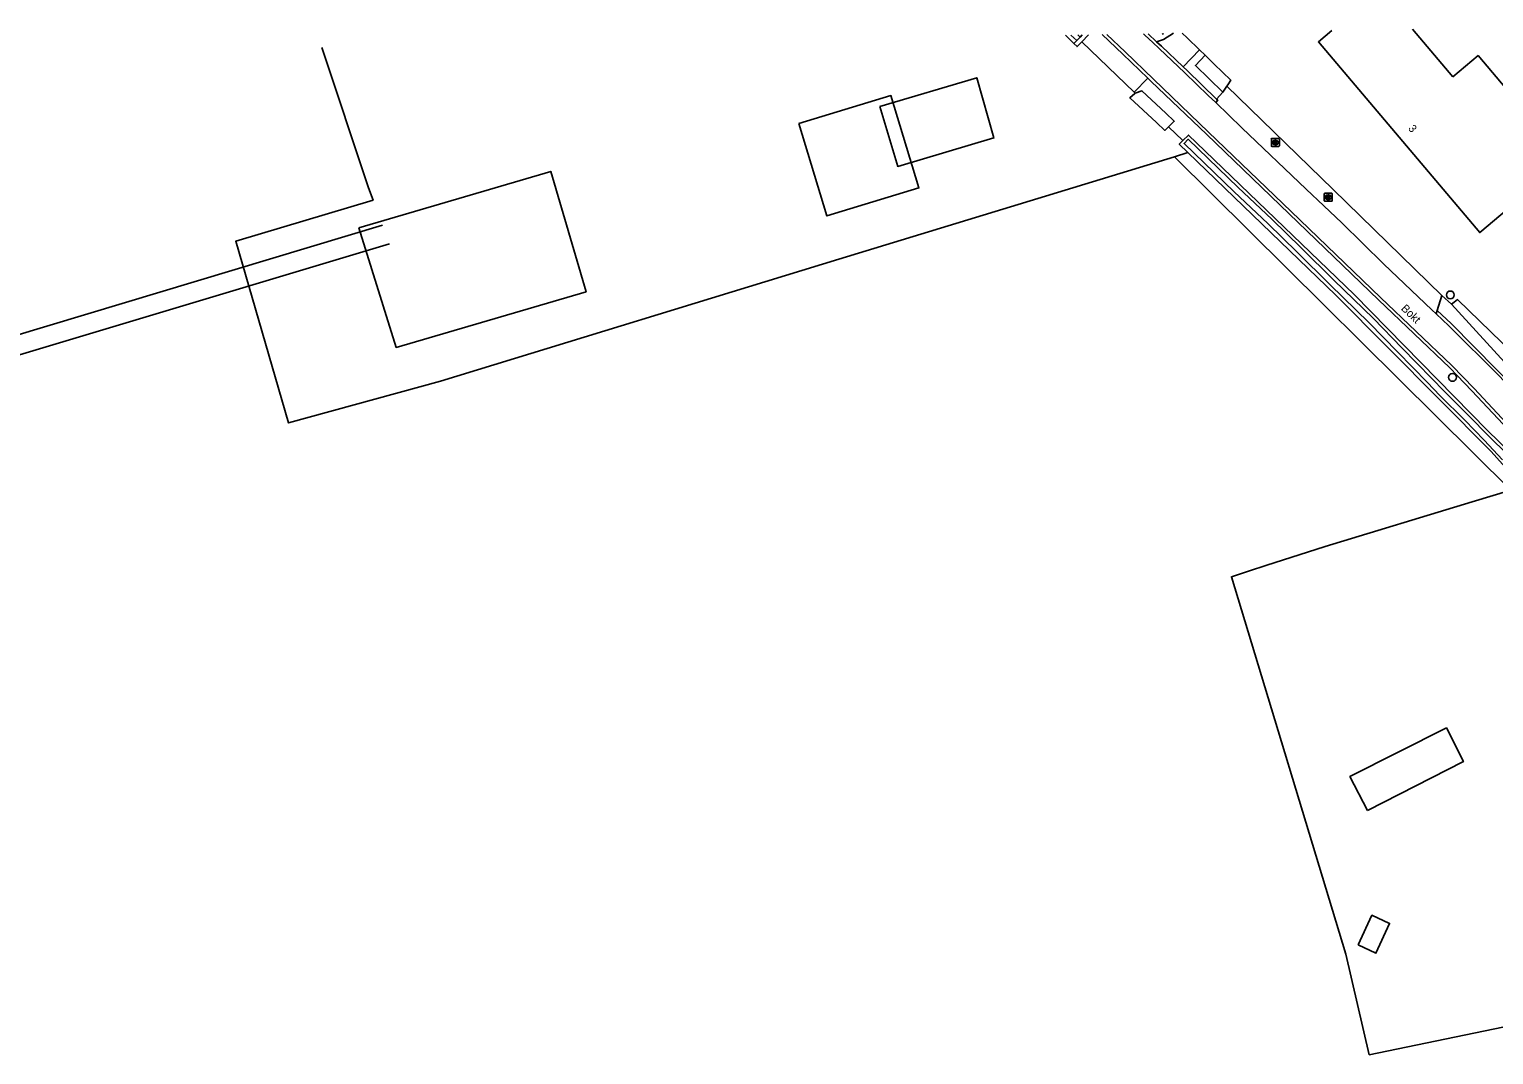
# Model space of a CAD drawing. Extents: x 162515 to 163909, y 388494 to 389773.
# Drawn here: x 162898.8 to 163081.8, y 389636 to 389764.2 of the extents above; entities that cross this region are included whole.
import ezdxf

# ---------------------------------------------------------------- set-up
doc = ezdxf.new("R2010")
doc.units = 0
for name, color, linetype in [('IMGEO_Berm_groen', 7, 'Continuous'), ('IMGEO_Boom', 7, 'Continuous'), ('IMGEO_Erf', 7, 'Continuous'), ('IMGEO_Grasland_agrarisch', 7, 'Continuous'), ('IMGEO_Grasland_overig', 7, 'Continuous'), ('IMGEO_Hek', 7, 'Continuous'), ('IMGEO_Inrit_halfverhard', 7, 'Continuous'), ('IMGEO_Kolk', 7, 'Continuous'), ('IMGEO_Openbare_ruimte_label', 7, 'Continuous'), ('IMGEO_Pand', 7, 'Continuous'), ('IMGEO_Pand_nummerreeks', 7, 'Continuous'), ('IMGEO_Pand_vergunning_verleend', 7, 'Continuous'), ('IMGEO_Rijbaan_lokaal_gesloten', 7, 'Continuous'), ('IMGEO_Rijbaan_lokaal_halfverhard', 7, 'Continuous'), ('IMGEO_Rijbaan_lokaal_open', 7, 'Continuous'), ('IMGEO_Rioolput', 7, 'Continuous'), ('IMGEO_Sloot', 7, 'Continuous'), ('IMGEO_Voetpad_open', 7, 'Continuous'), ('IMGEO_Waterloop', 7, 'Continuous')]:
    doc.layers.add(name, color=color, linetype=linetype)

msp = doc.modelspace()

# ---------------------------------------------------------------- linework, layer by layer
at = {"layer": 'IMGEO_Berm_groen'}
for points in [[(163029.38, 389762.44), (163029.72, 389762.79)], [(163030.36, 389762.63), (163029.78, 389762.04), (163029.38, 389762.44)], [(163030.14, 389763.23), (163030.41, 389763.51)], [(163045.09, 389761.62), (163045.78, 389760.95)]]:
    msp.add_lwpolyline(points, dxfattribs=at)
at = {"layer": 'IMGEO_Boom'}
for centre in [(163076.41, 389731), (163076.69, 389720.69)]:
    msp.add_circle(centre, 0.489, dxfattribs=at)
at = {"layer": 'IMGEO_Erf'}
for points in [[(163029.38, 389762.44), (163028.34, 389763.47)], [(163043.62, 389748.8), (163042.54, 389749.83), (163042.99, 389750.29)]]:
    msp.add_lwpolyline(points, dxfattribs=at)
at = {"layer": 'IMGEO_Grasland_agrarisch'}
for points in [[(163041.93, 389748.28), (163000, 389735.45), (162950.22, 389720.21), (162931.21, 389715.01), (162924.62, 389737.7), (162941.8, 389742.86), (162941.23, 389744.39), (162935.38, 389761.91)], [(163118.81, 389646.87), (163066.29, 389636.03), (163063.36, 389648.6), (163049.05, 389695.77), (163050.19, 389696.14), (163051.31, 389696.5), (163053.35, 389697.16), (163060.78, 389699.57), (163079.14, 389705.13), (163083.99, 389706.6)]]:
    msp.add_lwpolyline(points, dxfattribs=at)
at = {"layer": 'IMGEO_Grasland_overig'}
for points in [[(163037.03, 389756.22), (163036.89, 389756.36)], [(163042.99, 389750.29), (163041.21, 389752.03)], [(163042.99, 389750.29), (163043.68, 389750.98), (163044.68, 389750), (163064.38, 389731.06), (163081.07, 389714.04), (163085.27, 389709.98), (163089.56, 389704.66), (163097.34, 389691.77), (163097.11, 389691.63)], [(163041.93, 389748.28), (163043.62, 389748.8)], [(163083.99, 389706.6), (163041.93, 389748.28)], [(163043.62, 389748.8), (163062.1, 389730.98), (163081.53, 389711.41), (163085.44, 389707.04)], [(163075.36, 389730.92), (163076.55, 389729.85)]]:
    msp.add_lwpolyline(points, dxfattribs=at)
at = {"layer": 'IMGEO_Hek'}
for points in [[(162950.22, 389720.21), (163000, 389735.45), (163041.93, 389748.28), (163043.62, 389748.8)], [(162864.14, 389716.01), (162942.96, 389739.73)], [(162866.72, 389714.28), (162943.84, 389737.37)], [(163050.19, 389696.14), (163051.31, 389696.5), (163053.35, 389697.16), (163060.78, 389699.57), (163079.14, 389705.13), (163083.99, 389706.6), (163085.44, 389707.04)]]:
    msp.add_lwpolyline(points, dxfattribs=at)
at = {"layer": 'IMGEO_Inrit_halfverhard'}
for points in [[(163041.83, 389763.7), (163040.57, 389762.92), (163039.7, 389762.65)], [(163042.91, 389763.72), (163043.53, 389763.13), (163045.09, 389761.62)], [(163043.02, 389759.5), (163045.09, 389761.62)]]:
    msp.add_lwpolyline(points, dxfattribs=at)
at = {"layer": 'IMGEO_Kolk'}
for p, q in [((163054.05, 389749.63), (163054.05, 389750.48)), ((163054.12, 389750.55), (163054.97, 389750.55)), ((163054.97, 389749.55), (163054.12, 389749.55)), ((163054.53, 389750.33), (163054.56, 389750.33)), ((163054.56, 389749.77), (163054.53, 389749.77)), ((163055.05, 389750.48), (163055.05, 389749.63))]:
    msp.add_line(p, q, dxfattribs=at)
for points in [[(163054.05, 389749.63), (163054.05, 389750.48)], [(163054.12, 389750.55), (163054.97, 389750.55)], [(163054.97, 389749.55), (163054.12, 389749.55)], [(163054.37, 389750.25), (163054.49, 389750.25), (163054.49, 389750.1), (163054.62, 389750.25), (163054.78, 389750.25), (163054.64, 389750.1), (163054.79, 389749.85), (163054.64, 389749.85), (163054.55, 389750.02), (163054.49, 389749.95), (163054.49, 389749.85), (163054.37, 389749.85), (163054.37, 389750.25)], [(163055.05, 389750.48), (163055.05, 389749.63)]]:
    msp.add_lwpolyline(points, dxfattribs=at)
for centre, start, end in [((163054.12, 389750.48), 91.552, 178.448), ((163054.12, 389750.48), 91.552, 178.448), ((163054.12, 389749.63), 181.552, 268.448), ((163054.12, 389749.63), 181.552, 268.448), ((163054.97, 389750.48), 1.552, 88.448), ((163054.97, 389750.48), 1.552, 88.448), ((163054.97, 389749.63), 271.552, 358.448), ((163054.97, 389749.63), 271.552, 358.448)]:
    msp.add_arc(centre, 0.0765, start, end, dxfattribs=at)
for centre, major_axis, ratio, start_param, end_param in [((163054.53, 389750.05), (-0.387, 0.002), 0.722429, 4.712389, 7.853982), ((163054.56, 389750.05), (-0.39, 0.002), 0.717154, 1.570796, 4.712389)]:
    msp.add_ellipse(centre, major_axis=major_axis, ratio=ratio, start_param=start_param, end_param=end_param, dxfattribs=at)
at = {"layer": 'IMGEO_Pand'}
for points in [[(163076.73, 389758.25), (163079.88, 389760.91), (163090.88, 389747.9), (163080.1, 389738.79), (163059.94, 389762.63), (163061.6, 389764.03)], [(163071.7, 389764.2), (163076.73, 389758.25)], [(162994.98, 389752.41), (163006.51, 389755.91), (163010.01, 389744.38), (162998.48, 389740.88), (162994.98, 389752.41)], [(163066.05, 389666.55), (163063.87, 389670.8), (163075.92, 389676.87), (163078.06, 389672.66), (163066.05, 389666.55)], [(163064.9, 389649.75), (163067.11, 389648.72), (163068.83, 389652.44), (163066.62, 389653.47), (163064.9, 389649.75)]]:
    msp.add_lwpolyline(points, dxfattribs=at)
at = {"layer": 'IMGEO_Pand_vergunning_verleend'}
for points in [[(163005.14, 389754.55), (163017.23, 389758.14), (163019.37, 389750.63), (163007.35, 389747.07), (163005.14, 389754.55)], [(162940, 389739.39), (162963.99, 389746.43), (162968.4, 389731.4), (162944.68, 389724.44), (162940, 389739.39)]]:
    msp.add_lwpolyline(points, dxfattribs=at)
at = {"layer": 'IMGEO_Rijbaan_lokaal_gesloten'}
for points in [[(163100.84, 389691.74), (163099.39, 389693.96), (163095.98, 389699.17), (163094.02, 389702.1), (163091.83, 389705.15), (163088.44, 389709.34), (163083.99, 389714.39), (163079.4, 389719.3), (163076.61, 389722.17), (163067.71, 389730.69), (163056.54, 389741.42), (163046.2, 389751.36), (163039.32, 389757.98), (163035.76, 389761.38), (163033.47, 389763.56)], [(163047.09, 389755.05), (163046.17, 389755.93), (163043.25, 389758.74), (163040.02, 389761.8), (163039.24, 389762.55), (163038.25, 389763.47), (163038.07, 389763.64)], [(163074.65, 389728.64), (163074.12, 389729.14), (163068.12, 389734.84), (163062.86, 389740.02), (163060.62, 389742.15), (163058.38, 389744.23), (163050.35, 389751.88), (163047.09, 389755.05)], [(163087.55, 389715.37), (163084.74, 389718.53), (163082.54, 389720.88), (163076.25, 389727.13), (163074.65, 389728.64)]]:
    msp.add_lwpolyline(points, dxfattribs=at)
at = {"layer": 'IMGEO_Rijbaan_lokaal_halfverhard'}
for points in [[(163039.7, 389762.65), (163038.65, 389763.65)], [(163043.02, 389759.5), (163040.3, 389762.09), (163039.7, 389762.65)], [(163047.21, 389755.48), (163043.52, 389759.03), (163043.02, 389759.5)], [(163038.6, 389758.11), (163039.04, 389757.69), (163045.93, 389751.08), (163056.26, 389741.13), (163067.43, 389730.4), (163076.34, 389721.88), (163079.11, 389719.02), (163083.7, 389714.12), (163088.14, 389709.08), (163091.51, 389704.92), (163093.69, 389701.88), (163095.64, 389698.95), (163099.05, 389693.74), (163100.5, 389691.52), (163100.84, 389691.74)], [(163047.09, 389755.05), (163047.36, 389755.34), (163047.21, 389755.48)], [(163074.78, 389729.06), (163074.65, 389728.64)], [(163087.98, 389715.5), (163085.04, 389718.79), (163076.53, 389727.41), (163074.78, 389729.06)]]:
    msp.add_lwpolyline(points, dxfattribs=at)
at = {"layer": 'IMGEO_Rijbaan_lokaal_open'}
for points in [[(163031.18, 389763.52), (163030.36, 389762.63)], [(163030.36, 389762.63), (163036.89, 389756.36)], [(163032.9, 389763.55), (163035.48, 389761.09), (163038.6, 389758.11)], [(163036.89, 389756.36), (163038.6, 389758.11)]]:
    msp.add_lwpolyline(points, dxfattribs=at)
at = {"layer": 'IMGEO_Rioolput'}
for p, q in [((163060.66, 389742.78), (163060.66, 389743.63)), ((163060.74, 389743.71), (163061.59, 389743.71)), ((163061.59, 389742.71), (163060.74, 389742.71)), ((163061.15, 389743.49), (163061.18, 389743.49)), ((163061.17, 389742.93), (163061.15, 389742.93)), ((163061.67, 389743.63), (163061.67, 389742.78))]:
    msp.add_line(p, q, dxfattribs=at)
for points in [[(163060.66, 389742.78), (163060.66, 389743.63)], [(163060.74, 389743.71), (163061.59, 389743.71)], [(163061.59, 389742.71), (163060.74, 389742.71)], [(163061.25, 389743.41), (163061, 389743.41), (163061, 389743.01)], [(163061, 389743.01), (163061.13, 389743.01), (163061.13, 389743.17), (163061.14, 389743.17)], [(163061.18, 389743.33), (163061.13, 389743.33), (163061.13, 389743.25)], [(163061.13, 389743.25), (163061.18, 389743.25)], [(163061.18, 389743.14), (163061.25, 389743.01), (163061.39, 389743.01), (163061.33, 389743.13)], [(163061.67, 389743.63), (163061.67, 389742.78)]]:
    msp.add_lwpolyline(points, dxfattribs=at)
for centre, radius, start, end in [((163060.74, 389743.63), 0.0765, 91.552, 178.448), ((163060.74, 389743.63), 0.0765, 91.552, 178.448), ((163060.74, 389742.78), 0.0765, 181.552, 268.448), ((163060.74, 389742.78), 0.0765, 181.552, 268.448), ((163061.13, 389743.12), 0.0533, 26.0293, 88.6989), ((163061.18, 389743.23), 0.0964, 77.0061, 93.1865), ((163061.16, 389743.44), 0.19, 274.7715, 282.9687), ((163061.2, 389743.29), 0.0378, 276.6634, 79.6772), ((163061.25, 389743.3), 0.109, 350.3612, 89.416), ((163061.25, 389743.3), 0.112, 277.5842, 350.9817), ((163061.23, 389743.08), 0.108, 29.5134, 73.7905), ((163061.59, 389743.63), 0.0765, 1.552, 88.448), ((163061.59, 389743.63), 0.0765, 1.552, 88.448), ((163061.59, 389742.78), 0.0765, 271.552, 358.448), ((163061.59, 389742.78), 0.0765, 271.552, 358.448)]:
    msp.add_arc(centre, radius, start, end, dxfattribs=at)
for centre, major_axis, ratio, start_param, end_param in [((163061.15, 389743.21), (-0.387, 0.002), 0.722429, 4.712389, 7.853982), ((163061.18, 389743.21), (-0.39, 0.002), 0.717154, 1.570796, 4.712389)]:
    msp.add_ellipse(centre, major_axis=major_axis, ratio=ratio, start_param=start_param, end_param=end_param, dxfattribs=at)
at = {"layer": 'IMGEO_Sloot'}
for points in [[(163029, 389763.48), (163029.72, 389762.79)], [(163029.72, 389762.79), (163030.14, 389763.23)], [(163030.14, 389763.23), (163029.88, 389763.5)], [(163040.59, 389763.68), (163040.5, 389763.58), (163040.4, 389763.68)], [(163047.98, 389756.33), (163044.55, 389759.66), (163045.78, 389760.95)], [(163045.78, 389760.95), (163046.92, 389759.84), (163048.98, 389757.85), (163048.59, 389757.26), (163048.47, 389757.09)], [(163041.21, 389752.03), (163040.72, 389751.57), (163039.7, 389752.55), (163036.36, 389755.62), (163036.97, 389756.17), (163037.03, 389756.22)], [(163037.03, 389756.22), (163037.87, 389756.52), (163040.87, 389753.73), (163041.92, 389752.71), (163041.21, 389752.03)]]:
    msp.add_lwpolyline(points, dxfattribs=at)
at = {"layer": 'IMGEO_Voetpad_open'}
for points in [[(163048.47, 389757.09), (163047.98, 389756.33)], [(163048.47, 389757.09), (163049.91, 389755.71), (163061.77, 389744.16), (163075.36, 389730.92)], [(163047.98, 389756.33), (163047.21, 389755.48)], [(163075.36, 389730.92), (163074.78, 389729.06)]]:
    msp.add_lwpolyline(points, dxfattribs=at)
at = {"layer": 'IMGEO_Waterloop'}
for points in [[(163083.59, 389711.03), (163081.19, 389713.38), (163078.77, 389715.85), (163075.64, 389718.96), (163074.1, 389720.57), (163070.34, 389724.4), (163066.8, 389728.05), (163061.87, 389732.84), (163057.78, 389736.87), (163054.13, 389740.45), (163049.92, 389744.43), (163043.67, 389750.46), (163043.15, 389749.92), (163049.41, 389743.89), (163053.62, 389739.92), (163057.26, 389736.34), (163061.35, 389732.31), (163066.28, 389727.53), (163069.81, 389723.88), (163073.57, 389720.05), (163075.11, 389718.44), (163078.24, 389715.33), (163080.66, 389712.85), (163082.93, 389710.39)], [(163076.55, 389729.85), (163076.91, 389730.11), (163077.31, 389730.41), (163092.48, 389715.73), (163096.12, 389712.1)], [(163105.09, 389695.61), (163104.76, 389695.34), (163104.38, 389695.26), (163102.66, 389696.57), (163102.32, 389697.57), (163099.41, 389703.24), (163095.83, 389708.99), (163094.66, 389710.87), (163090.67, 389714.38), (163076.55, 389729.85)]]:
    msp.add_lwpolyline(points, dxfattribs=at)

# ---------------------------------------------------------------- texts
at = {"layer": 'IMGEO_Openbare_ruimte_label'}
msp.add_text('Bokt', height=1, rotation=316.4584, dxfattribs=at).set_placement((163070.19, 389729.21))
at = {"layer": 'IMGEO_Pand_nummerreeks'}
msp.add_text('3', height=1, rotation=310.2157, dxfattribs=at).set_placement((163071.09, 389751.77))

doc.saveas('drawing.dxf')
